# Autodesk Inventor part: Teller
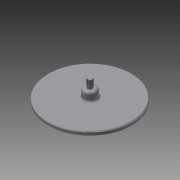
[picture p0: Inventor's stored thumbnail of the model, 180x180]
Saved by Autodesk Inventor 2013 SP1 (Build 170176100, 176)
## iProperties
Created: 2012-11
Part Number: Teller
Material: Allgemein
Document SubType Name: Modeling
Designer: macuser
Density: 1 g/cm^3
Author: macuser
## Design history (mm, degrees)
sketch "Skizze1"
  geometry: L1 (-140, 0)-(140, 0) reference; L2 (0, -140)-(0, 140) reference; C1 r 100 at (0, 0); 1 further point
  constraints: 1 centre point, 1 coincident
  dimensions: "d0" = 200 diameter of C1
extrude "Extrusion1" new body sketch "Skizze1" distance "d1" = 10; taper "d2" = 0 deg
sketch "Skizze2"
  geometry: C1 r 100 at (0, 0) reference; C2 r 15 at (0, 0)
  constraints: 1 centre point, 1 coincident
  dimensions: "d3" = 30 diameter of C2
extrude "Extrusion2" join sketch "Skizze2" distance "d4" = 20; taper "d5" = 0 deg
sketch "Skizze3"
  geometry: C1 r 15 at (0, 0) reference; C2 r 6 at (0, 0)
  constraints: 1 centre point, 1 coincident
  dimensions: "d7" = 12 diameter of C2
extrude "Extrusion3" join sketch "Skizze3" distance "d8" = 20; taper "d9" = 0 deg
feature "Gewinde1" dims "d10" = 20, "d11" = 5
fillet "Rundung1" dims "d12" = 5
fillet "Rundung2" dims "d13" = 5
chamfer "Fase1" distance "d14" = 2; stored, may be unused: second distance "d15" = 2, angle "d16" = 45 deg
node "Volumenkörper1"
